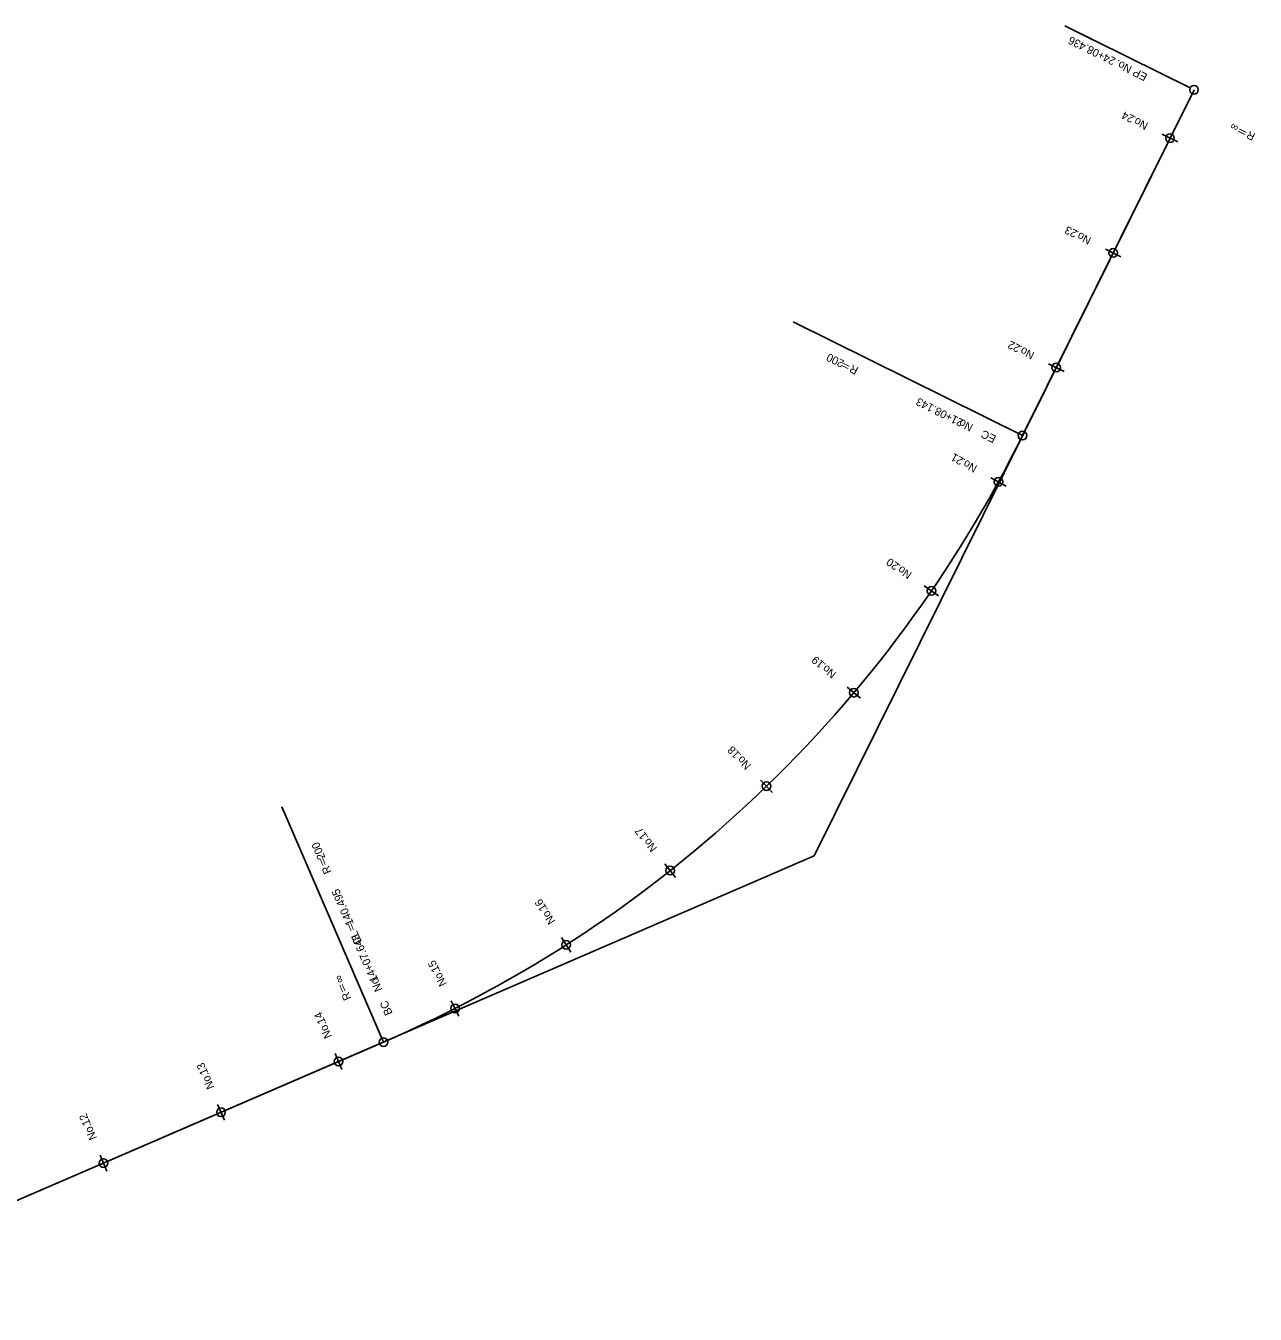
# Model space of a CAD drawing. Extents: x 46574 to 46965, y 10721 to 11034.
# Drawn here: x 46773.3 to 46965.4, y 10832.5 to 11033.7 of the extents above; entities that cross this region are included whole.
import ezdxf

# ---------------------------------------------------------------- set-up
doc = ezdxf.new("R2010")
doc.units = 0
for name, color, linetype in [('Default', 7, 'Continuous'), ('河川_通常部（地理院地図Vector）', 7, 'Continuous'), ('等高線等深線_等高線_計曲線通常部（地理院地図Vector）', 7, 'Continuous'), ('道路_通常部_通常部（地理院地図Vector）', 7, 'Continuous')]:
    doc.layers.add(name, color=color, linetype=linetype)

msp = doc.modelspace()

# ---------------------------------------------------------------- linework, layer by layer
at = {"layer": 'Default'}
for p, q in [((46955.22, 11024.01), (46935.66, 11033.7)), ((46935.66, 11033.7), (46940.14, 11031.48)), ((46896.47, 10904.04), (46955.82, 11023.71)), ((46955.82, 11023.71), (46955.82, 11023.71)), ((46952.07, 11016.15), (46952.07, 11016.15)), ((46943.19, 10998.23), (46943.19, 10998.23)), ((46929.03, 10969.69), (46893.2, 10987.47)), ((46934.3, 10980.31), (46934.3, 10980.31)), ((46929.03, 10969.69), (46929.03, 10969.69)), ((46925.26, 10962.47), (46925.26, 10962.47)), ((46914.8, 10945.44), (46914.8, 10945.44)), ((46902.68, 10929.54), (46902.68, 10929.54)), ((46889.03, 10914.93), (46889.03, 10914.93)), ((46829.19, 10874.97), (46813.33, 10911.69)), ((46730.82, 10832.46), (46896.47, 10904.04)), ((46874, 10901.75), (46874, 10901.75)), ((46857.72, 10890.14), (46857.72, 10890.14)), ((46840.37, 10880.21), (46840.37, 10880.21)), ((46829.19, 10874.97), (46829.19, 10874.97)), ((46822.17, 10871.93), (46822.17, 10871.93)), ((46803.81, 10864), (46803.81, 10864)), ((46785.45, 10856.07), (46785.45, 10856.07))]:
    msp.add_line(p, q, dxfattribs=at)
for centre in [(46955.82, 11023.71), (46952.07, 11016.15), (46943.19, 10998.23), (46934.3, 10980.31), (46929.03, 10969.69), (46925.26, 10962.47), (46914.8, 10945.44), (46902.68, 10929.54), (46889.03, 10914.93), (46874, 10901.75), (46857.72, 10890.14), (46840.37, 10880.21), (46829.19, 10874.97), (46822.17, 10871.93), (46803.81, 10864), (46785.45, 10856.07)]:
    msp.add_circle(centre, 0.675, dxfattribs=at)
msp.add_arc((46749.86, 11058.56), 200, 293.3699, 333.6189, dxfattribs=at)
at = {"layer": '等高線等深線_等高線_計曲線通常部（地理院地図Vector）'}
for p, q in [((46929.03, 10969.69), (46955.82, 11023.71)), ((46753.52, 10842.27), (46829.19, 10874.97))]:
    msp.add_line(p, q, dxfattribs=at)
msp.add_arc((46749.86, 11058.56), 200, 293.3699, 333.6189, dxfattribs=at)
at = {"layer": '道路_通常部_通常部（地理院地図Vector）'}
for p, q in [((46950.86, 11016.75), (46953.28, 11015.55)), ((46941.98, 10998.83), (46944.39, 10997.63)), ((46933.09, 10980.91), (46935.51, 10979.71)), ((46924.08, 10963.12), (46926.45, 10961.82)), ((46913.68, 10946.21), (46915.91, 10944.68)), ((46901.65, 10930.41), (46903.71, 10928.67)), ((46888.09, 10915.9), (46889.97, 10913.96)), ((46873.16, 10902.81), (46874.84, 10900.69)), ((46857, 10891.28), (46858.45, 10889.01)), ((46839.76, 10881.42), (46840.98, 10879.01)), ((46821.64, 10873.17), (46822.71, 10870.7)), ((46803.28, 10865.24), (46804.35, 10862.76)), ((46784.92, 10857.31), (46785.99, 10854.83))]:
    msp.add_line(p, q, dxfattribs=at)

# ---------------------------------------------------------------- texts
at = {"layer": 'Default'}
for s, rotation, p in [('24+08.436', 153.6189, (46943.69, 11028.58)), ('EP No.', 153.6189, (46948.65, 11026.12)), ('R＝∞', 153.6189, (46965.51, 11016.81)), ('200', 153.6189, (46901.29, 10981.36)), ('R＝', 153.6189, (46903.48, 10980.27)), ('21+08.143', 153.6189, (46919.92, 10972.12)), ('EC\u3000No.', 153.6189, (46925.02, 10969.59)), ('200', 113.3699, (46820.15, 10903.78)), ('R＝', 113.3699, (46821.11, 10901.54)), ('140.495', 113.3699, (46824.59, 10893.49)), ('CL＝', 113.3699, (46825.88, 10890.51)), ('14+07.648', 113.3699, (46828.4, 10884.68)), ('R＝∞', 113.3699, (46824.2, 10881.8)), ('BC\u3000No.', 113.3699, (46830.65, 10879.46))]:
    msp.add_text(s, height=1.25, rotation=rotation, dxfattribs=at).set_placement(p)
at = {"layer": '河川_通常部（地理院地図Vector）'}
for s, rotation, p in [('24', 153.6189, (46946.58, 11019.57)), ('No.', 153.6189, (46948.77, 11018.49)), ('23', 153.6189, (46937.7, 11001.65)), ('No.', 153.6189, (46939.88, 11000.57)), ('22', 153.6189, (46928.81, 10983.73)), ('No.', 153.6189, (46930.99, 10982.65)), ('21', 151.2859, (46919.92, 10966.11)), ('No.', 151.2859, (46922.06, 10964.94)), ('20', 145.5564, (46909.84, 10949.6)), ('No.', 145.5564, (46911.85, 10948.22)), ('19', 139.8268, (46898.16, 10934.17)), ('No.', 139.8268, (46900.03, 10932.6)), ('18', 134.0972, (46885, 10919.99)), ('No.', 134.0972, (46886.7, 10918.24)), ('17', 128.3676, (46870.49, 10907.19)), ('No.', 128.3676, (46872.01, 10905.28)), ('16', 122.638, (46854.78, 10895.9)), ('No.', 122.638, (46856.09, 10893.85)), ('15', 116.9085, (46838.02, 10886.24)), ('No.', 116.9085, (46839.12, 10884.06)), ('14', 113.3699, (46820.19, 10878.09)), ('No.', 113.3699, (46821.16, 10875.85)), ('13', 113.3699, (46801.83, 10870.16)), ('No.', 113.3699, (46802.8, 10867.92)), ('12', 113.3699, (46783.47, 10862.22)), ('No.', 113.3699, (46784.44, 10859.99))]:
    msp.add_text(s, height=1.25, rotation=rotation, dxfattribs=at).set_placement(p)

doc.saveas('drawing.dxf')
